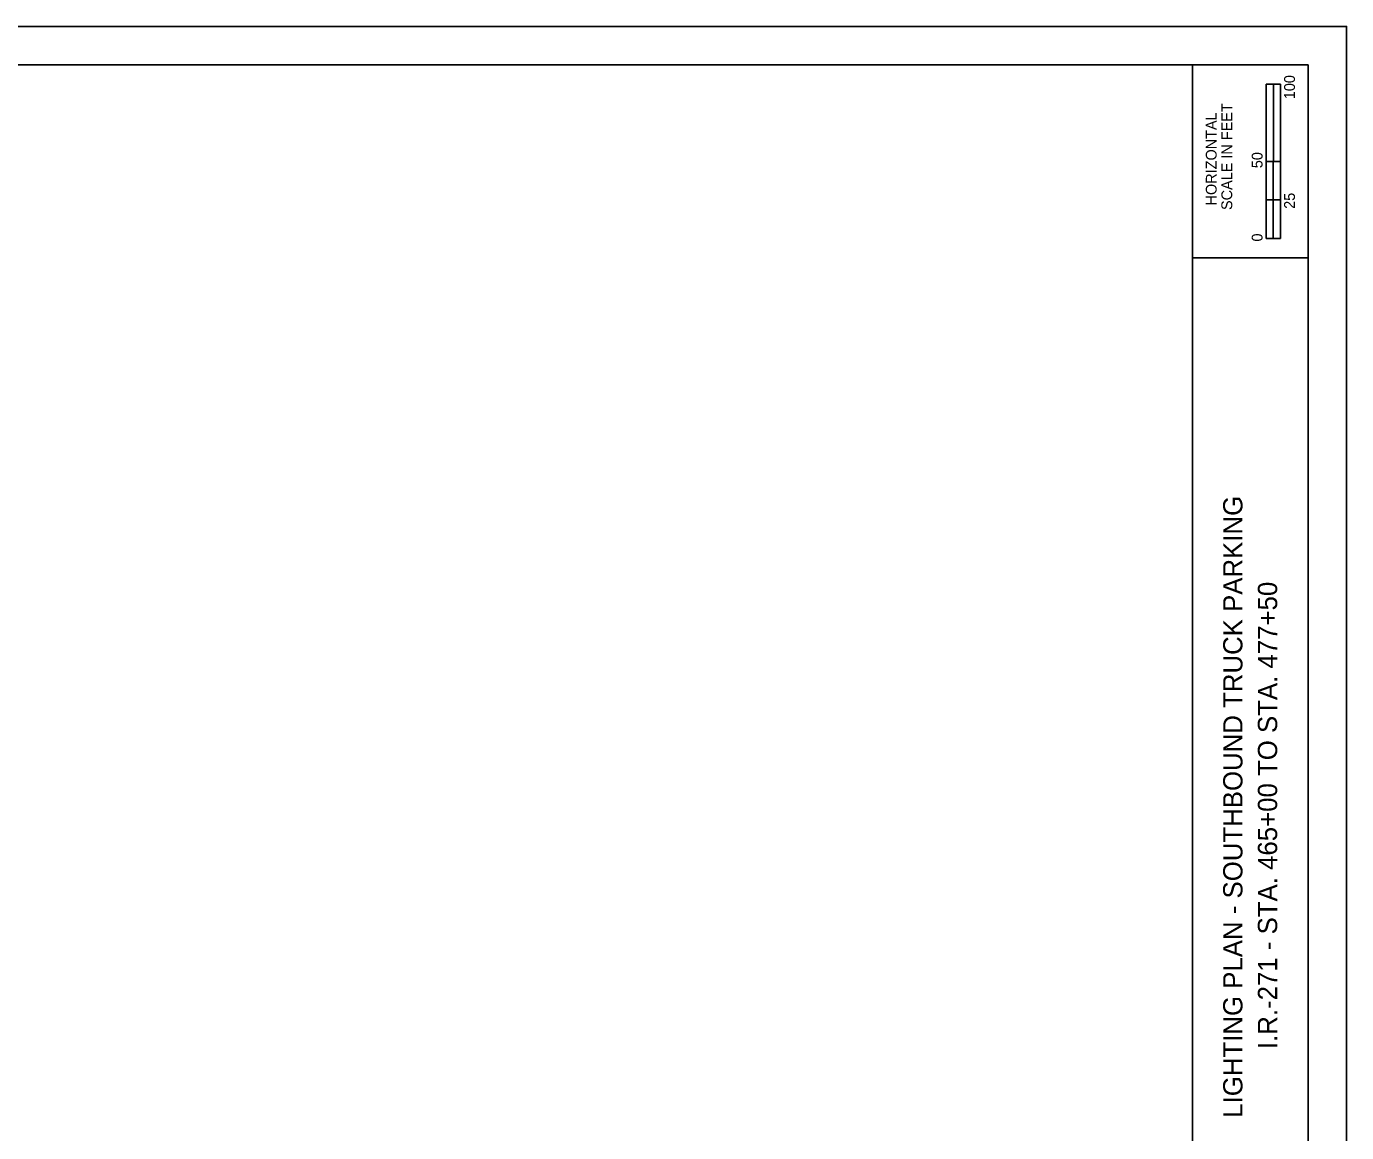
# Model space of a CAD drawing. Extents: x -0.2 to 34, y 6.6 to 28.6.
# Drawn here: x 16.88 to 34, y 14.27 to 28.61 of the extents above; entities that cross this region are included whole.
import ezdxf

# ---------------------------------------------------------------- set-up
doc = ezdxf.new("R2010")
doc.units = 0
for name, color, linetype in [('GE_X_Alignment', 7, 'Continuous'), ('SH_Border', 7, 'Continuous'), ('SH_Cut_Line', 7, 'Continuous'), ('SH_Data', 7, 'Continuous')]:
    doc.layers.add(name, color=color, linetype=linetype)

msp = doc.modelspace()

# ---------------------------------------------------------------- linework, layer by layer
at = {"layer": 'GE_X_Alignment'}
msp.add_lwpolyline([(1.5, 28.111), (32, 28.111), (32, 7.111), (1.5, 7.111)], close=True, dxfattribs=at)
at = {"layer": 'SH_Border'}
for p, q in [((32, 7.111), (32, 28.111)), ((32, 25.611), (33.5, 25.611))]:
    msp.add_line(p, q, dxfattribs=at)
msp.add_lwpolyline([(1.5, 28.111), (33.5, 28.111), (33.5, 7.111), (1.5, 7.111)], close=True, dxfattribs=at)
at = {"layer": 'SH_Cut_Line'}
msp.add_lwpolyline([(0, 6.611), (34, 6.611), (34, 28.611), (0, 28.611)], close=True, dxfattribs=at)
at = {"layer": 'SH_Data'}
for p, q in [((32.957, 25.861), (32.957, 27.861)), ((33.144, 27.861), (32.957, 27.861)), ((32.957, 26.861), (32.957, 27.861)), ((32.957, 27.861), (33.05, 27.861)), ((33.05, 27.861), (33.051, 27.861)), ((33.051, 27.861), (33.051, 26.861)), ((33.144, 27.861), (33.144, 25.861)), ((33.051, 26.861), (32.957, 26.861)), ((33.143, 26.861), (33.05, 26.861)), ((33.05, 26.861), (33.05, 26.361)), ((33.143, 26.361), (33.143, 26.861)), ((33.05, 26.361), (32.957, 26.361)), ((32.957, 26.361), (32.957, 25.861)), ((33.05, 25.861), (33.05, 26.361)), ((33.05, 26.361), (33.143, 26.361)), ((33.144, 25.861), (32.957, 25.861)), ((32.957, 25.861), (33.05, 25.861))]:
    msp.add_line(p, q, dxfattribs=at)

# ---------------------------------------------------------------- texts
for s, height, p in [('100', 0.14, (33.33, 27.667)), ('SCALE IN FEET', 0.14, (32.517, 26.231)), ('HORIZONTAL', 0.14, (32.315, 26.29)), ('50', 0.14, (32.91, 26.773)), ('25', 0.14, (33.33, 26.246)), ('0', 0.14, (32.91, 25.822)), ('LIGHTING PLAN - SOUTHBOUND TRUCK PARKING', 0.25, (32.65, 14.464)), ('I.R.-271 - STA. 465+00 TO STA. 477+50', 0.25, (33.1, 15.354))]:
    msp.add_text(s, height=height, rotation=90, dxfattribs=at).set_placement(p)

doc.saveas('drawing.dxf')
